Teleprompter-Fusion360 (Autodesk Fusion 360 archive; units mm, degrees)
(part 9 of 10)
sketch "Skizze105" plane through (0, 0, 0) normal (0, 0, -1) x axis (1, 0, 0)
  line L1 (47.0031, -126.3404) -> (155.5031, -126.3404)
  line L2 (35.0031, -31.3404) -> (35.0031, -114.3404)
  line L3 (155.5031, -19.3404) -> (47.0031, -19.3404)
  line L4 (167.5031, -114.3404) -> (167.5031, -31.3404)
  line L5 (191.5031, -31.3404) -> (191.5031, -114.3404)
  line L6 (312.0031, -19.3404) -> (203.5031, -19.3404)
  line L7 (324.0031, -114.3404) -> (324.0031, -31.3404)
  line L8 (203.5031, -126.3404) -> (312.0031, -126.3404)
  line L9 (137.0031, -323.7) -> (137.0031, -279.3404)
  line L10 (154.0031, -323.7) -> (137.0031, -323.7)
  line L11 (154.0031, -311.7) -> (154.0031, -323.7)
  line L12 (171.0031, -311.7) -> (154.0031, -311.7)
  line L13 (171.0031, -323.7) -> (171.0031, -311.7)
  line L14 (188.0031, -323.7) -> (171.0031, -323.7)
  line L15 (188.0031, -311.7) -> (188.0031, -323.7)
  line L16 (205.0031, -311.7) -> (188.0031, -311.7)
  line L17 (205.0031, -323.7) -> (205.0031, -311.7)
  line L18 (222.0031, -323.7) -> (205.0031, -323.7)
  line L19 (222.0031, -279.3404) -> (222.0031, -323.7)
  line L20 (374.0031, -255.3404) -> (246.0031, -255.3404)
  line L21 (374.0031, -240.1877) -> (374.0031, -255.3404)
  line L22 (366.2457, -240.1877) -> (374.0031, -240.1877)
  line L23 (362.0031, -220.3404) -> (362.0031, -235.9451)
  line L24 (361.0031, -220.3404) -> (362.0031, -220.3404)
  line L25 (358.0031, -167.3404) -> (358.0031, -217.3404)
  line L26 (362.0031, -164.3404) -> (361.0031, -164.3404)
  line L27 (362.0031, -134.383) -> (362.0031, -164.3404)
  line L28 (374.0031, -130.1404) -> (366.2457, -130.1404)
  line L29 (374.0031, -95.9404) -> (374.0031, -130.1404)
  line L30 (366.2457, -95.9404) -> (374.0031, -95.9404)
  line L31 (362.0031, -65.983) -> (362.0031, -91.6977)
  line L32 (374.0031, -61.7404) -> (366.2457, -61.7404)
  line L33 (374.0031, -27.5404) -> (374.0031, -61.7404)
  line L34 (366.2457, -27.5404) -> (374.0031, -27.5404)
  line L35 (362.0031, 2.417) -> (362.0031, -23.2977)
  line L36 (374.0031, 6.6596) -> (366.2457, 6.6596)
  line L37 (-2.9969, 18.6596) -> (362.0031, 18.6596)
  line L38 (-7.2396, 6.6596) -> (-14.9969, 6.6596)
  line L39 (-2.9969, -23.2977) -> (-2.9969, 2.417)
  line L40 (-14.9969, -27.5404) -> (-7.2396, -27.5404)
  line L41 (-14.9969, -61.7404) -> (-14.9969, -27.5404)
  line L42 (-7.2396, -61.7404) -> (-14.9969, -61.7404)
  line L43 (-2.9969, -91.6977) -> (-2.9969, -65.983)
  line L44 (-14.9969, -95.9404) -> (-7.2396, -95.9404)
  line L45 (-14.9969, -130.1404) -> (-14.9969, -95.9404)
  line L46 (-7.2396, -130.1404) -> (-14.9969, -130.1404)
  line L47 (-2.9969, -164.3404) -> (-2.9969, -134.383)
  line L48 (-2.9968, -164.3404) -> (-2.9969, -164.3404)
  line L49 (0.0031, -217.3404) -> (0.0031, -167.3404)
  line L50 (-2.9969, -220.3404) -> (-2.9968, -220.3404)
  line L51 (-2.9969, -235.9451) -> (-2.9969, -220.3404)
  line L52 (-14.9969, -240.1877) -> (-7.2396, -240.1877)
  line L53 (-14.9969, -255.3404) -> (-14.9969, -240.1877)
  line L54 (113.0031, -255.3404) -> (-14.9969, -255.3404)
  line L55 (159.8215, -317.5184) -> (154.0031, -311.7)
  line L56 (162.2315, -311.7) -> (154.0031, -311.7)
  line L57 (165.4986, -317.2045) -> (171.0031, -311.7)
  line L58 (178.7875, -311.7) -> (171.0031, -311.7)
  line L59 (193.6589, -317.3558) -> (188.0031, -311.7)
  line L60 (196.0016, -311.7) -> (188.0031, -311.7)
  line L61 (200.9258, -315.7773) -> (205.0031, -311.7)
  line L62 (210.7692, -311.7) -> (205.0031, -311.7)
  circle C1 centre (97.0031, -247.7641) radius 1.5
  circle C2 centre (179.5031, -138.3404) radius 1.5
  circle C3 centre (102.0031, -138.3404) radius 1.5
  circle C4 centre (262.0031, -247.7641) radius 1.5
  circle C5 centre (143.0031, -255.3404) radius 1.5
  circle C6 centre (257.0031, -138.3404) radius 1.5
  circle C7 centre (216.0031, -255.3404) radius 1.5
  circle C8 centre (179.4838, -56.3404) radius 1.5
  circle C9 centre (179.3775, -190) radius 20
  circle C10 centre (-8.9969, -113.0404) radius 4.5
  circle C11 centre (368.0031, -246.1877) radius 4.5
  circle C12 centre (368.0031, -44.6404) radius 4.5
  circle C13 centre (179.5031, -317.7) radius 4.5
  arc A1 centre (47.0031, -114.3404) radius 12 clockwise from (47.0031, -126.3404) to (35.0031, -114.3404)
  arc A2 centre (47.0031, -31.3404) radius 12 clockwise from (35.0031, -31.3404) to (47.0031, -19.3404)
  arc A3 centre (155.5031, -31.3404) radius 12 clockwise from (155.5031, -19.3404) to (167.5031, -31.3404)
  arc A4 centre (155.5031, -114.3404) radius 12 clockwise from (167.5031, -114.3404) to (155.5031, -126.3404)
  arc A5 centre (203.5031, -31.3404) radius 12 clockwise from (191.5031, -31.3404) to (203.5031, -19.3404)
  arc A6 centre (312.0031, -31.3404) radius 12 clockwise from (312.0031, -19.3404) to (324.0031, -31.3404)
  arc A7 centre (312.0031, -114.3404) radius 12 clockwise from (324.0031, -114.3404) to (312.0031, -126.3404)
  arc A8 centre (203.5031, -114.3404) radius 12 clockwise from (203.5031, -126.3404) to (191.5031, -114.3404)
  arc A9 centre (246.0031, -279.3404) radius 24 clockwise from (222.0031, -279.3404) to (246.0031, -255.3404)
  arc A10 centre (364.1244, -238.0664) radius 3 clockwise from (366.2457, -240.1877) to (362.0031, -235.9451)
  arc A11 centre (361.0031, -217.3404) radius 3 clockwise from (361.0031, -220.3404) to (358.0031, -217.3404)
  arc A12 centre (361.0031, -167.3404) radius 3 clockwise from (358.0031, -167.3404) to (361.0031, -164.3404)
  arc A13 centre (364.1244, -132.2617) radius 3 clockwise from (362.0031, -134.383) to (366.2457, -130.1404)
  arc A14 centre (364.1244, -93.8191) radius 3 clockwise from (366.2457, -95.9404) to (362.0031, -91.6977)
  arc A15 centre (364.1244, -63.8617) radius 3 clockwise from (362.0031, -65.983) to (366.2457, -61.7404)
  arc A16 centre (364.1244, -25.4191) radius 3 clockwise from (366.2457, -27.5404) to (362.0031, -23.2977)
  arc A17 centre (364.1244, 4.5383) radius 3 clockwise from (362.0031, 2.417) to (366.2457, 6.6596)
  arc A18 centre (362.0031, 6.6596) radius 12 clockwise from (362.0031, 18.6596) to (374.0031, 6.6596)
  arc A19 centre (-2.9969, 6.6596) radius 12 clockwise from (-14.9969, 6.6596) to (-2.9969, 18.6596)
  arc A20 centre (-5.1183, 4.5383) radius 3 clockwise from (-7.2396, 6.6596) to (-2.9969, 2.417)
  arc A21 centre (-5.1183, -25.4191) radius 3 clockwise from (-2.9969, -23.2977) to (-7.2396, -27.5404)
  arc A22 centre (-5.1183, -63.8617) radius 3 clockwise from (-7.2396, -61.7404) to (-2.9969, -65.983)
  arc A23 centre (-5.1183, -93.8191) radius 3 clockwise from (-2.9969, -91.6977) to (-7.2396, -95.9404)
  arc A24 centre (-5.1183, -132.2617) radius 3 clockwise from (-7.2396, -130.1404) to (-2.9969, -134.383)
  arc A25 centre (-2.9969, -167.3404) radius 3 clockwise from (-2.9968, -164.3404) to (0.0031, -167.3404)
  arc A26 centre (-2.9969, -217.3404) radius 3 clockwise from (0.0031, -217.3404) to (-2.9968, -220.3404)
  arc A27 centre (-5.1183, -238.0664) radius 3 clockwise from (-2.9969, -235.9451) to (-7.2396, -240.1877)
  arc A28 centre (113.0031, -279.3404) radius 24 clockwise from (113.0031, -255.3404) to (137.0031, -279.3404)
  circle C14 centre (213.5031, -317.7) radius 4.5
  circle C15 centre (145.5031, -317.7) radius 4.5
  circle C16 centre (368.0031, -113.0404) radius 4.5
  circle C17 centre (-8.9969, -44.6404) radius 4.5
  circle C18 centre (-8.9969, -246.1877) radius 4.5
  circle C19 centre (156.1597, -313.8567) radius 3.05
  circle C20 centre (168.8464, -313.8567) radius 3.05
  circle C21 centre (190.1597, -313.8567) radius 3.05
  circle C22 centre (202.8464, -313.8567) radius 3.05
  point P42 (154.0031, -311.7)
  point P130 (154.0031, -311.7)
  point P43 (171.0031, -311.7)
  point P133 (171.0031, -311.7)
  point P46 (188.0031, -311.7)
  point P136 (188.0031, -311.7)
  point P47 (205.0031, -311.7)
  point P139 (205.0031, -311.7)
  point P142 (156.1597, -313.8567)
  point P143 (168.8464, -313.8567)
  point P144 (190.1597, -313.8567)
  point P145 (202.8464, -313.8567)
  horizontal L56
  coincident P42 P130
  horizontal L58
  coincident P43 P133
  horizontal L60
  coincident P46 P136
  horizontal L62
  coincident P47 P139
  coincident L55 P142
  coincident L57 P143
  coincident L59 P144
  coincident L61 P145
  dimension "d621" angle L55 L56 = 45
  dimension "d622" angle L57 L58 = 135
  dimension "d623" angle L59 L60 = 45
  dimension "d624" angle L61 L62 = 135
  dimension "d625" diameter C19 = 6.1
  dimension "d626" diameter C20 = 6.1
  dimension "d627" diameter C21 = 6.1
  dimension "d628" diameter C22 = 6.1
  dimension "d629" distance P139 P145 = 3.05
  dimension "d630" distance P136 P144 = 3.05
  dimension "d631" distance P133 P143 = 3.05
  dimension "d632" distance P130 P142 = 3.05
extrude "Extrusion107" cut sketch "Skizze105" profile of L11 L12 L13 L15 L16 L17 C19 C20 C21 C22 against normal blind 17
sketch "Skizze106" plane through (0, 121.7, 0) normal (0, 1, 0) x axis (-1, 0, 0)
  line L1 (-137.0031, 150.455) -> (-137.0031, 163.3013)
  line L2 (14.9969, 150.455) -> (-137.0031, 150.455)
  line L3 (14.9969, 181.955) -> (14.9969, 150.455)
  line L4 (7.2396, 181.955) -> (14.9969, 181.955)
  line L5 (2.9969, 209.2124) -> (2.9969, 186.1976)
  line L6 (14.9969, 213.455) -> (7.2396, 213.455)
  line L7 (14.9969, 244.955) -> (14.9969, 213.455)
  line L8 (7.2396, 244.955) -> (14.9969, 244.955)
  line L9 (2.9969, 256.955) -> (2.9969, 249.1976)
  line L10 (-362.0031, 256.955) -> (2.9969, 256.955)
  line L11 (-362.0031, 249.1976) -> (-362.0031, 256.955)
  line L12 (-374.0031, 244.955) -> (-366.2457, 244.955)
  line L13 (-374.0031, 213.455) -> (-374.0031, 244.955)
  line L14 (-366.2457, 213.455) -> (-374.0031, 213.455)
  line L15 (-362.0031, 186.1976) -> (-362.0031, 209.2124)
  line L16 (-374.0031, 181.955) -> (-366.2457, 181.955)
  line L17 (-374.0031, 150.455) -> (-374.0031, 181.955)
  line L18 (-222.0031, 150.455) -> (-374.0031, 150.455)
  line L19 (-222.0031, 163.3017) -> (-222.0031, 150.455)
  line L20 (-222.0031, 202.455) -> (-222.0031, 189.1083)
  line L21 (-167.0031, 232.455) -> (-192.0031, 232.455)
  line L22 (-137.0031, 189.1087) -> (-137.0031, 202.455)
  line L23 (-247.0031, 138.455) -> (-247.0031, 146.1416)
  line L24 (-222.0031, 138.455) -> (-247.0031, 138.455)
  line L25 (-222.0031, 202.455) -> (-222.0031, 138.455)
  line L26 (-167.0031, 232.455) -> (-192.0031, 232.455)
  line L27 (-137.0031, 138.455) -> (-137.0031, 202.455)
  line L28 (-112.0031, 138.455) -> (-137.0031, 138.455)
  line L29 (-112.0031, 146.1416) -> (-112.0031, 138.455)
  line L30 (-87.0031, 150.455) -> (-107.6897, 150.455)
  line L31 (-87.0031, 232.955) -> (-87.0031, 150.455)
  line L32 (-248.0031, 256.955) -> (-111.0031, 256.955)
  line L33 (-272.0031, 150.455) -> (-272.0031, 232.955)
  line L34 (-251.3164, 150.455) -> (-272.0031, 150.455)
  line L35 (-338.0031, 220.955) -> (-338.0031, 186.455)
  line L36 (-362.0031, 29.6373) -> (-362.0031, 250.199)
  line L37 (-21.0031, 186.455) -> (-21.0031, 220.955)
  line L38 (2.9969, 250.199) -> (2.9969, 29.6373)
  line L39 (-284.0031, 186.455) -> (-284.0031, 220.955)
  line L40 (-75.0031, 186.455) -> (-75.0031, 220.955)
  line L41 (-296.0031, 232.955) -> (-326.0031, 232.955)
  line L42 (-296.0031, 174.455) -> (-326.0031, 174.455)
  line L43 (-242.1041, 232.955) -> (-272.0031, 232.955)
  line L44 (-87.0031, 232.955) -> (-110.271, 232.955)
  line L45 (-33.0031, 232.955) -> (-63.0031, 232.955)
  line L46 (-33.0031, 174.455) -> (-63.0031, 174.455)
  circle C1 centre (-247.0031, 191.955) radius 2
  circle C2 centre (-112.0031, 191.955) radius 2
  circle C3 centre (-247.0031, 231.955) radius 2
  circle C4 centre (-112.0031, 231.955) radius 2
  arc A1 centre (5.1183, 184.0763) radius 3 clockwise from (7.2396, 181.955) to (2.9969, 186.1976)
  arc A2 centre (5.1183, 211.3337) radius 3 clockwise from (2.9969, 209.2124) to (7.2396, 213.455)
  arc A3 centre (5.1183, 247.0763) radius 3 clockwise from (7.2396, 244.955) to (2.9969, 249.1976)
  arc A4 centre (-364.1244, 247.0763) radius 3 clockwise from (-362.0031, 249.1976) to (-366.2457, 244.955)
  arc A5 centre (-364.1244, 211.3337) radius 3 clockwise from (-366.2457, 213.455) to (-362.0031, 209.2124)
  arc A6 centre (-364.1244, 184.0763) radius 3 clockwise from (-362.0031, 186.1976) to (-366.2457, 181.955)
  arc A7 centre (-217.2525, 176.205) radius 13.75 clockwise from (-222.0031, 163.3017) to (-222.0031, 189.1083)
  arc A8 centre (-192.0031, 202.455) radius 30 clockwise from (-222.0031, 202.455) to (-192.0031, 232.455)
  arc A9 centre (-167.0031, 202.455) radius 30 clockwise from (-167.0031, 232.455) to (-137.0031, 202.455)
  arc A10 centre (-141.7525, 176.205) radius 13.75 clockwise from (-137.0031, 189.1087) to (-137.0031, 163.3013)
  arc A11 centre (-249.1597, 148.2983) radius 3.05 clockwise from (-251.3164, 150.455) to (-247.0031, 146.1416)
  arc A12 centre (-192.0031, 202.455) radius 30 clockwise from (-222.0031, 202.455) to (-192.0031, 232.455)
  arc A13 centre (-167.0031, 202.455) radius 30 clockwise from (-167.0031, 232.455) to (-137.0031, 202.455)
  arc A14 centre (-109.8464, 148.2983) radius 3.05 clockwise from (-112.0031, 146.1416) to (-107.6897, 150.455)
  arc A15 centre (-111.0031, 232.955) radius 24 clockwise from (-111.0031, 256.955) to (-87.0031, 232.955)
  arc A16 centre (-248.0031, 232.955) radius 24 clockwise from (-272.0031, 232.955) to (-248.0031, 256.955)
  circle C5 centre (-124.5031, 144.455) radius 1.5
  circle C6 centre (-234.5031, 144.455) radius 1.5
  circle C7 centre (-247.0031, 231.955) radius 5
  circle C8 centre (-112.0031, 231.955) radius 5
  circle C9 centre (-112.0031, 191.955) radius 5
  circle C10 centre (-247.0031, 191.955) radius 5
  arc A17 centre (-326.0031, 220.955) radius 12 clockwise from (-338.0031, 220.955) to (-326.0031, 232.955)
  arc A18 centre (-296.0031, 220.955) radius 12 clockwise from (-296.0031, 232.955) to (-284.0031, 220.955)
  arc A19 centre (-296.0031, 186.455) radius 12 clockwise from (-284.0031, 186.455) to (-296.0031, 174.455)
  arc A20 centre (-326.0031, 186.455) radius 12 clockwise from (-326.0031, 174.455) to (-338.0031, 186.455)
  arc A21 centre (-63.0031, 220.955) radius 12 clockwise from (-75.0031, 220.955) to (-63.0031, 232.955)
  arc A22 centre (-33.0031, 220.955) radius 12 clockwise from (-33.0031, 232.955) to (-21.0031, 220.955)
  arc A23 centre (-33.0031, 186.455) radius 12 clockwise from (-21.0031, 186.455) to (-33.0031, 174.455)
  arc A24 centre (-63.0031, 186.455) radius 12 clockwise from (-63.0031, 174.455) to (-75.0031, 186.455)
  point P82 (-242.1041, 232.955)
  point P83 (-110.271, 232.955)
  perpendicular L10 L35
  perpendicular L2 L37
  vertical L39
  parallel L31 L40
  perpendicular L37 L41
  perpendicular L37 L42
  collinear L41 L43
  coincident C7 P82
  collinear L43 L44
  collinear L44 L45
  coincident C4 P83
  tangent L35 A17
  tangent L41 A17
  tangent L41 A18
  tangent L39 A18
  equal A17 A18
  tangent L39 A19
  tangent L42 A19
  equal A17 A19
  tangent L42 A20
  tangent L35 A20
  equal A17 A20
  tangent L40 A21
  tangent L45 A21
  equal A17 A21
  tangent L45 A22
  tangent L37 A22
  equal A17 A22
  tangent L37 A23
  tangent L46 A23
  equal A17 A23
  tangent L46 A24
  tangent L40 A24
  equal A17 A24
  dimension "d635" distance L35 L36 = 24
  dimension "d636" distance L37 L38 = 24 (= "d635")
  dimension "d637" distance L31 L40 = 12
  dimension "d638" distance L33 L39 = 12
  dimension "d639" distance L10 L41 = 24
  dimension "d640" distance L2 L42 = 24
  dimension "d641" radius A17 = 12
extrude "Extrusion108" cut sketch "Skizze106" profile of L35 L37 L39 L40 L45 L46 A17 A18 A19 A20 A21 A22 A23 A24 against normal blind 20
sketch "Skizze107" plane through (0, 323.7, 0) normal (0, 1, 0) x axis (-1, 0, 0)
  line L1 (-205.0031, 0) -> (-205.0031, 7.6866)
  line L2 (-188.0031, 0) -> (-205.0031, 0)
  line L3 (-188.0031, 7.6866) -> (-188.0031, 0)
  line L4 (-175.3164, 12) -> (-183.6897, 12)
  line L5 (-171.0031, 0) -> (-171.0031, 7.6866)
  line L6 (-154.0031, 0) -> (-171.0031, 0)
  line L7 (-154.0031, 7.6866) -> (-154.0031, 0)
  line L8 (-137.0031, 12) -> (-149.6897, 12)
  line L9 (-137.0031, 138.455) -> (-137.0031, 12)
  line L10 (-149.6897, 138.455) -> (-137.0031, 138.455)
  line L11 (-154.0031, 150.455) -> (-154.0031, 142.7684)
  line L12 (-171.0031, 150.455) -> (-154.0031, 150.455)
  line L13 (-171.0031, 142.7684) -> (-171.0031, 150.455)
  line L14 (-183.6897, 138.455) -> (-175.3164, 138.455)
  line L15 (-188.0031, 150.455) -> (-188.0031, 142.7684)
  line L16 (-205.0031, 150.455) -> (-188.0031, 150.455)
  line L17 (-205.0031, 142.7684) -> (-205.0031, 150.455)
  line L18 (-222.0031, 138.455) -> (-209.3164, 138.455)
  line L19 (-222.0031, 12) -> (-222.0031, 138.455)
  line L20 (-209.3164, 12) -> (-222.0031, 12)
  line L21 (-171.0031, 114.455) -> (-188.0031, 114.455)
  line L22 (-161.0031, 46) -> (-161.0031, 104.455)
  line L23 (-188.0031, 36) -> (-171.0031, 36)
  line L24 (-198.0031, 104.455) -> (-198.0031, 46)
  circle C1 centre (-196.5031, 6) radius 4.5
  circle C2 centre (-162.5031, 144.455) radius 4.5
  circle C3 centre (-196.5031, 144.455) radius 4.5
  circle C4 centre (-162.5031, 6) radius 4.5
  arc A1 centre (-207.1597, 9.8433) radius 3.05 clockwise from (-209.3164, 12) to (-205.0031, 7.6866)
  arc A2 centre (-185.8464, 9.8433) radius 3.05 clockwise from (-188.0031, 7.6866) to (-183.6897, 12)
  arc A3 centre (-173.1597, 9.8433) radius 3.05 clockwise from (-175.3164, 12) to (-171.0031, 7.6866)
  arc A4 centre (-151.8464, 9.8433) radius 3.05 clockwise from (-154.0031, 7.6866) to (-149.6897, 12)
  arc A5 centre (-151.8464, 140.6117) radius 3.05 clockwise from (-149.6897, 138.455) to (-154.0031, 142.7684)
  arc A6 centre (-173.1597, 140.6117) radius 3.05 clockwise from (-171.0031, 142.7684) to (-175.3164, 138.455)
  arc A7 centre (-185.8464, 140.6117) radius 3.05 clockwise from (-183.6897, 138.455) to (-188.0031, 142.7684)
  arc A8 centre (-207.1597, 140.6117) radius 3.05 clockwise from (-205.0031, 142.7684) to (-209.3164, 138.455)
  arc A9 centre (-188.0031, 104.455) radius 10 clockwise from (-198.0031, 104.455) to (-188.0031, 114.455)
  arc A10 centre (-171.0031, 104.455) radius 10 clockwise from (-171.0031, 114.455) to (-161.0031, 104.455)
  arc A11 centre (-171.0031, 46) radius 10 clockwise from (-161.0031, 46) to (-171.0031, 36)
  arc A12 centre (-188.0031, 46) radius 10 clockwise from (-188.0031, 36) to (-198.0031, 46)
  horizontal L21
  vertical L22
  horizontal L23
  vertical L24
  tangent L24 A9
  tangent L21 A9
  tangent L21 A10
  tangent L22 A10
  equal A9 A10
  tangent L22 A11
  tangent L23 A11
  equal A9 A11
  tangent L23 A12
  tangent L24 A12
  equal A9 A12
  dimension "d644" distance L8 L23 = 24
  dimension "d645" distance L18 L21 = 24 (= "d644")
  dimension "d646" distance L19 L24 = 24
  dimension "d647" distance L9 L22 = 24 (= "d646")
  dimension "d648" radius A9 = 10
extrude "Extrusion109" cut sketch "Skizze107" profile of L21 L22 L23 L24 A9 A10 A11 A12 against normal blind 20
sketch "Skizze108" plane through (0, 133.7, 0) normal (0, 1, 0) x axis (-1, 0, 0)
  line L1 (-247.0031, 138.455) -> (-247.0031, 146.1416)
  line L2 (-222.0031, 138.455) -> (-247.0031, 138.455)
  line L3 (-222.0031, 202.455) -> (-222.0031, 138.455)
  line L4 (-167.0031, 232.455) -> (-192.0031, 232.455)
  line L5 (-137.0031, 138.455) -> (-137.0031, 202.455)
  line L6 (-112.0031, 138.455) -> (-137.0031, 138.455)
  line L7 (-112.0031, 146.1416) -> (-112.0031, 138.455)
  line L8 (-87.0031, 150.455) -> (-107.6897, 150.455)
  line L9 (-87.0031, 232.955) -> (-87.0031, 150.455)
  line L10 (-248.0031, 256.955) -> (-111.0031, 256.955)
  line L11 (-272.0031, 150.455) -> (-272.0031, 232.955)
  line L12 (-251.3164, 150.455) -> (-272.0031, 150.455)
  line L13 (-228.0031, 202.455) -> (-228.0031, 144.455)
  line L14 (-167.0031, 238.455) -> (-192.0031, 238.455)
  line L15 (-131.0031, 144.455) -> (-131.0031, 202.455)
  line L16 (-118.0398, 144.455) -> (-131.0031, 144.455)
  line L17 (-93.0031, 156.455) -> (-105.9258, 156.455)
  line L18 (-93.0031, 232.955) -> (-93.0031, 156.455)
  line L19 (-248.0031, 250.955) -> (-111.0031, 250.955)
  line L20 (-266.0031, 156.455) -> (-266.0031, 232.955)
  line L21 (-253.0803, 156.455) -> (-266.0031, 156.455)
  line L22 (-228.0031, 144.455) -> (-240.9664, 144.455)
  arc A1 centre (-249.1597, 148.2983) radius 3.05 clockwise from (-251.3164, 150.455) to (-247.0031, 146.1416)
  arc A2 centre (-192.0031, 202.455) radius 30 clockwise from (-222.0031, 202.455) to (-192.0031, 232.455)
  arc A3 centre (-167.0031, 202.455) radius 30 clockwise from (-167.0031, 232.455) to (-137.0031, 202.455)
  arc A4 centre (-109.8464, 148.2983) radius 3.05 clockwise from (-112.0031, 146.1416) to (-107.6897, 150.455)
  arc A5 centre (-111.0031, 232.955) radius 24 clockwise from (-111.0031, 256.955) to (-87.0031, 232.955)
  arc A6 centre (-248.0031, 232.955) radius 24 clockwise from (-272.0031, 232.955) to (-248.0031, 256.955)
  circle C1 centre (-124.5031, 144.455) radius 1.5
  circle C2 centre (-234.5031, 144.455) radius 1.5
  circle C3 centre (-247.0031, 231.955) radius 5
  circle C4 centre (-112.0031, 231.955) radius 5
  circle C5 centre (-112.0031, 191.955) radius 5
  circle C6 centre (-247.0031, 191.955) radius 5
  circle C7 centre (-179.5031, 189.955) radius 48.5
  arc A7 centre (-192.0031, 202.455) radius 36 clockwise from (-228.0031, 202.455) to (-192.0031, 238.455)
  arc A8 centre (-167.0031, 202.455) radius 36 clockwise from (-167.0031, 238.455) to (-131.0031, 202.455)
  arc A9 centre (-109.8464, 148.2983) radius 9.05 clockwise from (-118.0398, 144.455) to (-105.9258, 156.455)
  arc A10 centre (-111.0031, 232.955) radius 18 clockwise from (-111.0031, 250.955) to (-93.0031, 232.955)
  arc A11 centre (-248.0031, 232.955) radius 18 clockwise from (-266.0031, 232.955) to (-248.0031, 250.955)
  arc A12 centre (-249.1597, 148.2983) radius 9.05 clockwise from (-253.0803, 156.455) to (-240.9664, 144.455)
  tangent C7 L14
  tangent C7 L15
  tangent C7 L13
  dimension "d651" = 6
extrude "Extrusion110" cut sketch "Skizze108" profile of L3 A2 L4 A3 L5 C7 against normal blind 60
copy_paste_bodies "Körper kopieren/einfügen2"
move "Verschieben3"
move "Verschieben4"
sketch "Skizze109" plane through (0, 133.7, 0) normal (0, 1, 0) x axis (-1, 0, 0)
  line L1 (-137.0031, 138.455) -> (-137.0031, 166.5884)
  line L2 (-112.0031, 138.455) -> (-137.0031, 138.455)
  line L3 (-112.0031, 146.1416) -> (-112.0031, 138.455)
  line L4 (-87.0031, 150.455) -> (-107.6897, 150.455)
  line L5 (-87.0031, 232.955) -> (-87.0031, 150.455)
  line L6 (-248.0031, 256.955) -> (-111.0031, 256.955)
  line L7 (-272.0031, 150.455) -> (-272.0031, 232.955)
  line L8 (-251.3164, 150.455) -> (-272.0031, 150.455)
  line L9 (-247.0031, 138.455) -> (-247.0031, 146.1416)
  line L10 (-222.0031, 138.455) -> (-247.0031, 138.455)
  line L11 (-222.0031, 166.5884) -> (-222.0031, 138.455)
  line L12 (-87.0031, 150.455) -> (-272.0031, 150.455)
  arc A1 centre (-179.5031, 189.955) radius 48.5 clockwise from (-222.0031, 166.5884) to (-137.0031, 166.5884)
  arc A2 centre (-109.8464, 148.2983) radius 3.05 clockwise from (-112.0031, 146.1416) to (-107.6897, 150.455)
  arc A3 centre (-111.0031, 232.955) radius 24 clockwise from (-111.0031, 256.955) to (-87.0031, 232.955)
  arc A4 centre (-248.0031, 232.955) radius 24 clockwise from (-272.0031, 232.955) to (-248.0031, 256.955)
  arc A5 centre (-249.1597, 148.2983) radius 3.05 clockwise from (-251.3164, 150.455) to (-247.0031, 146.1416)
  circle C1 centre (-124.5031, 144.455) radius 1.5
  circle C2 centre (-234.5031, 144.455) radius 1.5
  circle C3 centre (-247.0031, 231.955) radius 5
  circle C4 centre (-112.0031, 231.955) radius 5
  circle C5 centre (-112.0031, 191.955) radius 5
  circle C6 centre (-247.0031, 191.955) radius 5
  point P17 (-272.0031, 150.455)
  point P29 (-272.0031, 150.455)
  point P10 (-87.0031, 150.455)
  point P30 (-87.0031, 150.455)
  coincident P17 P29
  coincident P10 P30
extrude "Extrusion111" cut sketch "Skizze109" profile of L1 L2 L3 A2 A5 L9 L10 L11 C1 C2 L12 against normal blind 30
sketch "Skizze110" plane through (0, 133.7, 0) normal (0, 1, 0) x axis (-1, 0, 0)
  line L1 (-222.0031, 150.455) -> (-247.0031, 150.455)
  line L2 (-222.0031, 166.5884) -> (-222.0031, 150.455)
  line L3 (-137.0031, 150.455) -> (-137.0031, 166.5884)
  line L4 (-112.0031, 150.455) -> (-137.0031, 150.455)
  line L5 (-87.0031, 150.455) -> (-107.6897, 150.455)
  line L6 (-87.0031, 232.955) -> (-87.0031, 150.455)
  line L7 (-248.0031, 256.955) -> (-111.0031, 256.955)
  line L8 (-272.0031, 150.455) -> (-272.0031, 232.955)
  line L9 (-251.3164, 150.455) -> (-272.0031, 150.455)
  line L10 (-141.7525, 162.455) -> (-217.2525, 162.455)
  line L11 (-217.2525, 189.955) -> (-141.7525, 189.955)
  line L12 (-217.2525, 190.155) -> (-141.7525, 190.155)
  line L13 (-141.7525, 162.255) -> (-217.2525, 162.255)
  line L14 (-235.5415, 189.955) -> (-217.2525, 189.955)
  line L15 (-122.7226, 190.155) -> (-235.5415, 189.955)
  line L16 (-137.0031, 150.455) -> (-222.0031, 150.455)
  line L17 (-87.0031, 150.455) -> (-272.0031, 150.455)
  circle C1 centre (-247.0031, 191.955) radius 5
  circle C2 centre (-112.0031, 191.955) radius 5
  circle C3 centre (-112.0031, 231.955) radius 5
  circle C4 centre (-247.0031, 231.955) radius 5
  arc A1 centre (-179.5031, 189.955) radius 48.5 clockwise from (-222.0031, 166.5884) to (-137.0031, 166.5884)
  arc A2 centre (-109.8464, 148.2983) radius 3.05 clockwise from (-112.0031, 150.455) to (-107.6897, 150.455)
  arc A3 centre (-111.0031, 232.955) radius 24 clockwise from (-111.0031, 256.955) to (-87.0031, 232.955)
  arc A4 centre (-248.0031, 232.955) radius 24 clockwise from (-272.0031, 232.955) to (-248.0031, 256.955)
  arc A5 centre (-249.1597, 148.2983) radius 3.05 clockwise from (-251.3164, 150.455) to (-247.0031, 150.455)
  arc A6 centre (-217.2525, 176.205) radius 13.75 clockwise from (-217.2525, 162.455) to (-217.2525, 189.955)
  arc A7 centre (-141.7525, 176.205) radius 13.75 clockwise from (-141.7525, 189.955) to (-141.7525, 162.455)
  arc A8 centre (-141.7525, 176.205) radius 13.95 clockwise from (-141.7525, 190.155) to (-141.7525, 162.255)
  arc A9 centre (-217.2525, 176.205) radius 13.95 clockwise from (-217.2525, 162.255) to (-217.2525, 190.155)
  point P25 (-217.2525, 189.955)
  point P37 (-217.2525, 189.955)
  point P7 (-222.0031, 150.455)
  point P40 (-222.0031, 150.455)
  point P11 (-137.0031, 150.455)
  point P41 (-137.0031, 150.455)
  point P22 (-272.0031, 150.455)
  point P42 (-272.0031, 150.455)
  point P15 (-87.0031, 150.455)
  point P43 (-87.0031, 150.455)
  coincident P25 P37
  tangent A6 L14
  coincident P7 P40
  coincident P11 P41
  coincident P22 P42
  coincident P15 P43
  dimension "d656" = 0.2
chamfer "Fase16" distance 1.5
chamfer "Fase17" distance 1.5
extrude "Extrusion113" add of existing geometry blind 12
sketch "Skizze111" plane through (0, 121.7, 0) normal (0, -1, 0) x axis (1, 0, 0)
  line L1 (272.0031, 150.455) -> (251.3164, 150.455)
  line L2 (272.0031, 232.955) -> (272.0031, 150.455)
  line L3 (111.0031, 256.955) -> (248.0031, 256.955)
  line L4 (87.0031, 150.455) -> (87.0031, 232.955)
  line L5 (107.6897, 150.455) -> (87.0031, 150.455)
  line L6 (112.0031, 138.455) -> (112.0031, 150.455)
  line L7 (137.0031, 138.455) -> (112.0031, 138.455)
  line L8 (137.0031, 166.5884) -> (137.0031, 138.455)
  line L9 (222.0031, 138.455) -> (222.0031, 166.5884)
  line L10 (247.0031, 138.455) -> (222.0031, 138.455)
  line L11 (247.0031, 150.455) -> (247.0031, 138.455)
  arc A1 centre (249.1597, 148.2983) radius 3.05 clockwise from (247.0031, 150.455) to (251.3164, 150.455)
  arc A2 centre (248.0031, 232.955) radius 24 clockwise from (248.0031, 256.955) to (272.0031, 232.955)
  arc A3 centre (111.0031, 232.955) radius 24 clockwise from (87.0031, 232.955) to (111.0031, 256.955)
  arc A4 centre (109.8464, 148.2983) radius 3.05 clockwise from (107.6897, 150.455) to (112.0031, 150.455)
  arc A5 centre (179.5031, 189.955) radius 48.5 clockwise from (137.0031, 166.5884) to (222.0031, 166.5884)
  circle C1 centre (112.0031, 191.955) radius 2
  circle C2 centre (112.0031, 231.955) radius 2
  circle C3 centre (247.0031, 191.955) radius 2
  circle C4 centre (247.0031, 231.955) radius 2
  circle C5 centre (249.1597, 148.2983) radius 3.05
  circle C6 centre (109.8464, 148.2983) radius 3.05
  point P2 (251.3164, 150.455)
  point P14 (112.0031, 150.455)
  concentric A1 C5
  coincident P2 C5
  concentric A4 C6
  coincident P14 C6
extrude "Extrusion114" cut sketch "Skizze111" profile of L6 L11 C5 C6 against normal blind 20
sketch "Skizze112" plane through (0, 121.7, 0) normal (0, -1, 0) x axis (1, 0, 0)
  line L1 (112.0031, 138.455) -> (112.0031, 146.1416)
  line L2 (137.0031, 138.455) -> (112.0031, 138.455)
  line L3 (137.0031, 166.5884) -> (137.0031, 138.455)
  line L4 (222.0031, 138.455) -> (222.0031, 166.5884)
  line L5 (247.0031, 138.455) -> (222.0031, 138.455)
  line L6 (247.0031, 146.1416) -> (247.0031, 138.455)
  line L7 (272.0031, 150.455) -> (251.3164, 150.455)
  line L8 (272.0031, 232.955) -> (272.0031, 150.455)
  line L9 (111.0031, 256.955) -> (248.0031, 256.955)
  line L10 (87.0031, 150.455) -> (87.0031, 232.955)
  line L11 (107.6897, 150.455) -> (87.0031, 150.455)
  line L12 (87.0031, 150.455) -> (272.0031, 150.455)
  line L13 (112.0031, 150.455) -> (112.0031, 138.455)
  line L14 (247.0031, 150.455) -> (247.0031, 138.455)
  line L15 (137.0031, 150.455) -> (112.0031, 138.455)
  line L16 (112.0031, 150.455) -> (137.0031, 138.455)
  line L17 (247.0031, 150.455) -> (222.0031, 138.455)
  line L18 (222.0031, 150.455) -> (247.0031, 138.455)
  circle C1 centre (247.0031, 231.955) radius 2
  circle C2 centre (247.0031, 191.955) radius 2
  circle C3 centre (112.0031, 231.955) radius 2
  circle C4 centre (112.0031, 191.955) radius 2
  arc A1 centre (109.8464, 148.2983) radius 3.05 clockwise from (107.6897, 150.455) to (112.0031, 146.1416)
  arc A2 centre (179.5031, 189.955) radius 48.5 clockwise from (137.0031, 166.5884) to (222.0031, 166.5884)
  arc A3 centre (249.1597, 148.2983) radius 3.05 clockwise from (247.0031, 146.1416) to (251.3164, 150.455)
  arc A4 centre (248.0031, 232.955) radius 24 clockwise from (248.0031, 256.955) to (272.0031, 232.955)
  arc A5 centre (111.0031, 232.955) radius 24 clockwise from (87.0031, 232.955) to (111.0031, 256.955)
  circle C5 centre (234.5031, 144.455) radius 1.5
  circle C6 centre (124.5031, 144.455) radius 1.5
  point P19 (272.0031, 150.455)
  point P27 (272.0031, 150.455)
  point P26 (87.0031, 150.455)
  point P28 (87.0031, 150.455)
  point P9 (112.0031, 138.455)
  point P29 (112.0031, 138.455)
  point P30 (112.0031, 150.455)
  point P15 (247.0031, 138.455)
  point P31 (247.0031, 138.455)
  point P32 (247.0031, 150.455)
  point P33 (137.0031, 150.455)
  point P10 (137.0031, 138.455)
  point P34 (137.0031, 138.455)
  point P14 (222.0031, 138.455)
  point P35 (222.0031, 138.455)
  point P36 (247.0031, 138.455)
  point P38 (234.5031, 144.455)
  point P39 (124.5031, 144.455)
  coincident P19 P27
  coincident P26 P28
  coincident P9 P29
  midpoint A1 P30
  coincident P15 P31
  midpoint A3 P32
  coincident L12 P33
  coincident L3 P33
  coincident P10 P34
  coincident P14 P35
  coincident P15 P36
  midpoint L18 P38
  midpoint L16 P39
  dimension "d665" diameter C5 = 3
  dimension "d666" diameter C6 = 3
extrude "Extrusion115" cut sketch "Skizze112" profile of C5 C6 against normal blind 15
chamfer "Fase18" distance 3
chamfer "Fase19" distance 2
chamfer "Fase20" distance 1
offset_faces "Flächen versetzen5" distance -0.1
sketch "Skizze113" plane through (0, 225.3404, 0) normal (0, 1, 0) x axis (-1, 0, 0)
  line L1 (-355.5031, 14.2) -> (-3.5031, 14.2)
  line L2 (-355.5031, 4.8) -> (-355.5031, 14.2)
  line L3 (-3.5031, 4.8) -> (-355.5031, 4.8)
  line L4 (-3.5031, 14.2) -> (-3.5031, 4.8)
  line L5 (-359.0031, 4.8) -> (-359.0031, 14.2)
  line L6 (-0.0031, 14.2) -> (-0.0031, 4.8)
  line L7 (-325.0031, 4) -> (-325.0031, 14.2)
  line L8 (-301.0031, 4) -> (-301.0031, 14.2)
  line L9 (-3.5031, 4) -> (-355.5031, 4)
  line L10 (-301.0031, 4) -> (-325.0031, 4)
  line L11 (-301.0031, 8) -> (-301.0031, 4)
  line L12 (-325.0031, 8) -> (-301.0031, 8)
  line L13 (-325.0031, 4) -> (-325.0031, 8)
  line L14 (-179.5031, 22.1076) -> (-179.5031, 4)
  line L15 (-34.0031, 4) -> (-34.0031, 8)
  line L16 (-34.0031, 8) -> (-58.0031, 8)
  line L17 (-58.0031, 4) -> (-58.0031, 14.2)
  line L18 (-34.0031, 4) -> (-34.0031, 14.2)
  line L19 (-58.0031, 4) -> (-34.0031, 4)
  point P10 (-325.0031, 14.2)
  point P11 (-301.0031, 14.2)
  point P14 (-325.0031, 4)
  point P15 (-301.0031, 4)
  point P19 (-179.5031, 4)
  point P26 (-34.0031, 14.2)
  point P24 (-58.0031, 14.2)
  point P22 (-34.0031, 4)
  point P25 (-58.0031, 4)
  point P16 (-301.0031, 4)
  point P27 (-58.0031, 4)
  point P17 (-301.0031, 8)
  point P23 (-58.0031, 8)
  point P18 (-325.0031, 8)
  point P21 (-34.0031, 8)
  coincident L1 P10
  perpendicular L3 L7
  coincident L1 P11
  perpendicular L3 L8
  coincident L9 P14
  coincident L9 P15
  horizontal L10
  vertical L11
  horizontal L12
  vertical L13
  midpoint L9 P19
  perpendicular L1 L14
  symmetric P10 L14 P26
  symmetric P11 L14 P24
  symmetric P14 L14 P22
  symmetric P15 L14 P25
  symmetric P16 L14 P27
  symmetric P17 L14 P23
  symmetric P18 L14 P21
  dimension "d673" distance L5 L7 = 34
  dimension "d674" distance L5 L8 = 58
  dimension "d675" distance P14 P18 = 4
extrude "Extrusion117" new body sketch "Skizze113" profile of L3 L7 L8 L9 L10 L11 L12 L13 L15 L16 L17 L18 L19 along normal blind 2 bodies "gummi-nupsi1", "gummi-nupsi2"
sketch "Skizze114" plane through (0, 0, 4) normal (0, 0, 1) x axis (-1, 0, 0)
  line L1 (2.9968, -220.3404) -> (2.9969, -220.3404)
  line L2 (-0.0031, -167.3404) -> (-0.0031, -217.3404)
  line L3 (2.9969, -164.3404) -> (2.9968, -164.3404)
  line L4 (2.9969, -150.3404) -> (2.9969, -164.3404)
  line L5 (-362.0031, -150.3404) -> (2.9969, -150.3404)
  line L6 (-362.0031, -164.3404) -> (-362.0031, -150.3404)
  line L7 (-361.0031, -164.3404) -> (-362.0031, -164.3404)
  line L8 (-358.0031, -217.3404) -> (-358.0031, -167.3404)
  line L9 (-362.0031, -220.3404) -> (-361.0031, -220.3404)
  line L10 (-362.0031, -226.3404) -> (-362.0031, -220.3404)
  line L11 (2.9969, -226.3404) -> (-362.0031, -226.3404)
  line L12 (2.9969, -220.3404) -> (2.9969, -226.3404)
  line L13 (-34.0031, -225.3404) -> (-58.0031, -225.3404)
  line L14 (-325.0031, -225.3404) -> (-301.0031, -225.3404)
  line L15 (-325.0031, -227.3404) -> (-301.0031, -227.3404)
  line L16 (-58.0031, -227.3404) -> (-34.0031, -227.3404)
  line L17 (-179.5031, -180.5742) -> (-179.5031, -226.3404)
  line L18 (-58.0031, -227.3404) -> (-34.0031, -227.3404)
  line L19 (-58.0031, -227.3404) -> (-34.0031, -227.3404)
  line L20 (-58.0031, -225.3404) -> (-58.0031, -227.3404)
  line L21 (-34.0031, -225.3404) -> (-58.0031, -225.3404)
  line L22 (-34.0031, -227.3404) -> (-34.0031, -225.3404)
  line L23 (-46.0031, -224.9775) -> (-46.0031, -227.3404)
  line L24 (-60.2391, -226.3404) -> (-31.767, -226.3404)
  line L25 (-298.767, -226.3404) -> (-327.2391, -226.3404)
  line L26 (-301.0031, -227.3404) -> (-325.0031, -227.3404)
  circle C1 centre (-179.3775, -190) radius 20
  arc A1 centre (2.9969, -217.3404) radius 3 clockwise from (2.9968, -220.3404) to (-0.0031, -217.3404)
  arc A2 centre (2.9969, -167.3404) radius 3 clockwise from (-0.0031, -167.3404) to (2.9968, -164.3404)
  arc A3 centre (-361.0031, -167.3404) radius 3 clockwise from (-361.0031, -164.3404) to (-358.0031, -167.3404)
  arc A4 centre (-361.0031, -217.3404) radius 3 clockwise from (-358.0031, -217.3404) to (-361.0031, -220.3404)
  arc A5 centre (-58.0031, -224.3404) radius 3 clockwise from (-58.0031, -227.3404) to (-60.2391, -226.3404)
  arc A6 centre (-34.0031, -224.3404) radius 3 clockwise from (-31.767, -226.3404) to (-34.0031, -227.3404)
  arc A7 centre (-325.0031, -224.3404) radius 3 clockwise from (-325.0031, -227.3404) to (-327.2391, -226.3404)
  arc A8 centre (-301.0031, -224.3404) radius 3 clockwise from (-298.767, -226.3404) to (-301.0031, -227.3404)
  point P31 (-179.5031, -226.3404)
  point P29 (-34.0031, -227.3404)
  point P33 (-34.0031, -227.3404)
  point P30 (-58.0031, -227.3404)
  point P34 (-58.0031, -227.3404)
  point P23 (-58.0031, -225.3404)
  point P36 (-58.0031, -225.3404)
  point P38 (-34.0031, -224.3404)
  point P39 (-46.0031, -227.3404)
  point P42 (-60.2391, -226.3404)
  point P43 (-31.767, -226.3404)
  point P47 (-325.0031, -227.3404)
  point P51 (-301.0031, -227.3404)
  point P48 (-325.0031, -227.3404)
  point P49 (-301.0031, -227.3404)
  point P45 (-298.767, -226.3404)
  point P44 (-327.2391, -226.3404)
  midpoint L11 P31
  perpendicular L11 L17
  coincident P29 P33
  coincident P30 P34
  horizontal L19
  vertical L20
  horizontal L21
  vertical L22
  coincident P23 P36
  tangent L19 A6
  coincident L22 P38
  midpoint L16 P39
  perpendicular L19 L23
  symmetric L23 A5 A6
  coincident L11 P42
  coincident L11 P43
  symmetric P29 L17 P47
  symmetric P30 L17 P51
  symmetric L17 P33 P48
  symmetric L17 P34 P49
  symmetric L17 P42 P45
  symmetric L17 A5 A8
  symmetric L17 A6 A7
  symmetric L17 P43 P44
  dimension "d680" diameter A6 = 6
extrude "Extrusion118" cut sketch "Skizze114" profile of L11 L15 L16 L18 L19 L20 L22 A6 A5 L24 L25 A7 L26 A8 along normal blind 9
sketch "Skizze115" plane through (-2.9969, 0, 0) normal (1, 0, 0) x axis (0, 1, 0)
  line L1 (-14.1296, 239.4473) -> (-16.2056, 241.5232)
  line L2 (-13.069, 240.508) -> (-14.1296, 239.4473)
  line L3 (-18.6596, 263) -> (-18.6596, 251.0692)
  line L4 (-18.6596, 263.0692) -> (-18.659, 263.0686)
  line L5 (-18.659, 263.0698) -> (-18.6596, 263.0692)
  line L6 (-10.2487, 267) -> (-14.6596, 267)
  line L7 (-3.2487, 268) -> (-3.2487, 267)
  line L8 (-4.7487, 268.5) -> (-3.2487, 268)
  line L9 (-14.6596, 268.5) -> (-4.7487, 268.5)
  line L10 (-20.1596, 251.0692) -> (-20.1596, 263)
  line L11 (-4.7893, 268.25) -> (-3.4987, 267.8198)
  line L12 (-14.6596, 268.25) -> (-4.7893, 268.25)
  line L13 (-19.9096, 251.0692) -> (-19.9096, 263)
  line L14 (-14.1296, 239.8008) -> (-16.0288, 241.7)
  line L15 (-13.2457, 240.6847) -> (-14.3064, 239.6241)
  line L16 (-18.9096, 262.9656) -> (-18.9096, 251.0692)
  line L17 (-19.0132, 263.0692) -> (-18.9096, 262.9656)
  line L18 (-18.9059, 263.1764) -> (-19.0132, 263.0692)
  line L19 (-9.9891, 267.25) -> (-14.6596, 267.25)
  line L20 (-3.4987, 268.0833) -> (-3.4987, 267)
  arc A1 centre (-15.5438, 242.9828) radius 3.5 clockwise from (-17.4864, 245.8942) to (-13.069, 240.508)
  arc A2 centre (-6.6596, 251.0692) radius 12 clockwise from (-17.4864, 245.8942) to (-18.6596, 251.0692)
  arc A3 centre (-14.6596, 263) radius 4 clockwise from (-18.6596, 263) to (-18.659, 263.0686)
  arc A4 centre (-14.6596, 263) radius 4 clockwise from (-18.659, 263.0698) to (-14.6596, 267)
  arc A5 centre (-6.7487, 267) radius 3.5 clockwise from (-3.2487, 267) to (-10.2487, 267)
  arc A6 centre (-14.6596, 263) radius 5.5 clockwise from (-20.1596, 263) to (-14.6596, 268.5)
  arc A7 centre (-6.6596, 251.0692) radius 13.5 clockwise from (-16.2056, 241.5232) to (-20.1596, 251.0692)
  arc A8 centre (-14.6596, 263) radius 5.25 clockwise from (-19.9096, 263) to (-14.6596, 268.25)
  arc A9 centre (-6.6596, 251.0692) radius 13.25 clockwise from (-16.0288, 241.7) to (-19.9096, 251.0692)
  arc A10 centre (-15.5438, 242.9828) radius 3.25 clockwise from (-17.579, 245.5167) to (-13.2457, 240.6847)
  arc A11 centre (-6.6596, 251.0692) radius 12.25 clockwise from (-17.579, 245.5167) to (-18.9096, 251.0692)
  arc A12 centre (-14.6596, 263) radius 4.25 clockwise from (-18.9059, 263.1764) to (-14.6596, 267.25)
  arc A13 centre (-6.7487, 267) radius 3.25 clockwise from (-3.4987, 267) to (-9.9891, 267.25)
  point P45 (-14.3064, 239.6241)
  point P31 (-14.1296, 239.8008)
  point P46 (-3.4987, 268.0833)
  point P23 (-3.4987, 267.8198)
  parallel L8 L11
  parallel L9 L12
  concentric A6 A8
  parallel L10 L13
  concentric A7 A9
  parallel L1 L14
  parallel L2 L15
  concentric A1 A10
  concentric A2 A11
  parallel L3 L16
  parallel L4 L17
  parallel L5 L18
  concentric A4 A12
  parallel L6 L19
  concentric A5 A13
  parallel L7 L20
  tangent L13 A9
  tangent L12 A8
  tangent L15 A10
  tangent A8 L13
  tangent A9 L14
  tangent A11 L16
  tangent A12 L19
  tangent A13 L20
  coincident L1 P45
  coincident P31 L15
  coincident L8 P46
  coincident P23 L20
extrude "Extrusion119" cut sketch "Skizze115" profile of L1 L2 A1 A2 L3 A3 L4 L5 A4 L6 A5 L7 L8 L16 L15 L20 A10 A11 L17 L18 A12 L19 A13 against normal blind 12
sketch "Skizze116" plane through (362.0031, 0, 0) normal (-1, 0, 0) x axis (0, -1, 0)
  line L1 (3.2948, 266.4342) -> (9.4921, 268.5)
  line L2 (14.6596, 267) -> (10.2487, 267)
  line L3 (18.6596, 263.0692) -> (18.659, 263.0698)
  line L4 (18.659, 263.0686) -> (18.6596, 263.0692)
  line L5 (18.6596, 251.0692) -> (18.6596, 263)
  line L6 (14.1296, 239.4473) -> (13.069, 240.508)
  line L7 (16.2056, 241.5232) -> (14.1296, 239.4473)
  line L8 (20.1596, 263) -> (20.1596, 251.0692)
  line L9 (9.4921, 268.5) -> (14.6596, 268.5)
  line L10 (14.6596, 267.25) -> (9.9891, 267.25)
  line L11 (3.5826, 266.2666) -> (9.5327, 268.25)
  line L12 (9.5327, 268.25) -> (14.6596, 268.25)
  line L13 (19.9096, 263) -> (19.9096, 251.0692)
  line L14 (16.0288, 241.7) -> (14.1296, 239.8008)
  line L15 (14.3064, 239.6241) -> (13.2457, 240.6847)
  line L16 (18.9096, 251.0692) -> (18.9096, 262.9656)
  line L17 (18.9096, 262.9656) -> (19.0132, 263.0692)
  line L18 (19.0132, 263.0692) -> (18.9059, 263.1764)
  line L19 (18.9096, 262.9656) -> (18.9059, 263.1764)
  arc A1 centre (6.7487, 267) radius 3.5 clockwise from (10.2487, 267) to (3.2948, 266.4342)
  arc A2 centre (14.6596, 263) radius 4 clockwise from (14.6596, 267) to (18.659, 263.0698)
  arc A3 centre (14.6596, 263) radius 4 clockwise from (18.659, 263.0686) to (18.6596, 263)
  arc A4 centre (6.6596, 251.0692) radius 12 clockwise from (18.6596, 251.0692) to (17.4864, 245.8942)
  arc A5 centre (15.5438, 242.9828) radius 3.5 clockwise from (13.069, 240.508) to (17.4864, 245.8942)
  arc A6 centre (6.6596, 251.0692) radius 13.5 clockwise from (20.1596, 251.0692) to (16.2056, 241.5232)
  arc A7 centre (14.6596, 263) radius 5.5 clockwise from (14.6596, 268.5) to (20.1596, 263)
  arc A8 centre (14.6596, 263) radius 4.25 clockwise from (14.6596, 267.25) to (18.9059, 263.1764)
  arc A9 centre (6.7487, 267) radius 3.25 clockwise from (9.9891, 267.25) to (3.5352, 266.5144)
  arc A10 centre (14.6596, 263) radius 5.25 clockwise from (14.6596, 268.25) to (19.9096, 263)
  arc A11 centre (6.6596, 251.0692) radius 13.25 clockwise from (19.9096, 251.0692) to (16.0288, 241.7)
  arc A12 centre (15.5438, 242.9828) radius 3.25 clockwise from (13.2457, 240.6847) to (17.579, 245.5167)
  arc A13 centre (6.6596, 251.0692) radius 12.25 clockwise from (18.9096, 251.0692) to (17.579, 245.5167)
  point P43 (14.3064, 239.6241)
  point P35 (14.1296, 239.8008)
  point P44 (3.5352, 266.5144)
  point P27 (3.5826, 266.2666)
  concentric A2 A8
  parallel L2 L10
  concentric A1 A9
  parallel L1 L11
  parallel L9 L12
  concentric A7 A10
  parallel L8 L13
  concentric A6 A11
  parallel L7 L14
  parallel L6 L15
  concentric A5 A12
  concentric A4 A13
  parallel L5 L16
  parallel L4 L17
  parallel L3 L18
  tangent L13 A11
  tangent A8 L10
  tangent A10 L13
  tangent L12 A10
  tangent A11 L14
  tangent L15 A12
  tangent A13 L16
  coincident L7 P43
  coincident P35 L15
  coincident L1 P44
  coincident P27 A9
extrude "Extrusion120" cut sketch "Skizze116" profile of L1 A1 L2 A2 L3 L4 A3 L5 A4 A5 L6 L7 L10 A8 A9 L15 A12 A13 L16 L19 against normal blind 12
offset_faces "Flächen versetzen6" distance 5
offset_faces "Flächen versetzen7" distance 5
offset_faces "Flächen versetzen8" distance -0.1
offset_faces "Flächen versetzen9" distance -0.1
offset_faces "Flächen versetzen10" distance -0.1
offset_faces "Flächen versetzen11" distance -0.1
offset_faces "Flächen versetzen12" distance -0.1
offset_faces "Flächen versetzen13" distance -0.1
offset_faces "Flächen versetzen14" distance -0.1
offset_faces "Flächen versetzen15" distance -0.1
offset_faces "Flächen versetzen16" distance -0.1
offset_faces "Flächen versetzen17" distance -0.1
offset_faces "Flächen versetzen18" distance -0.1
offset_faces "Flächen versetzen19" distance -0.1
offset_faces "Flächen versetzen20" distance -0.1
offset_faces "Flächen versetzen21" distance -0.1
offset_faces "Flächen versetzen22" distance -0.1
offset_faces "Flächen versetzen23" distance -0.1
offset_faces "Flächen versetzen24" distance -0.1
offset_faces "Flächen versetzen25" distance -0.1
offset_faces "Flächen versetzen26" distance -0.1
offset_faces "Flächen versetzen27" distance -0.1
offset_faces "Flächen versetzen28" distance -0.1
offset_faces "Flächen versetzen29" distance -0.1
offset_faces "Flächen versetzen30" distance -0.1
offset_faces "Flächen versetzen31" distance -0.1
sketch "Skizze118" plane through (0, 121.7, 0) normal (0, 1, 0) x axis (-1, 0, 0)
  line L1 (-137.0031, 150.455) -> (-137.0031, 163.3013)
  line L2 (14.9969, 150.455) -> (-137.0031, 150.455)
  line L3 (14.9969, 181.955) -> (14.9969, 150.455)
  line L4 (7.2396, 181.955) -> (14.9969, 181.955)
  line L5 (2.9969, 209.2124) -> (2.9969, 186.1976)
  line L6 (14.9969, 213.455) -> (7.2396, 213.455)
  line L7 (14.9969, 244.955) -> (14.9969, 213.455)
  line L8 (7.2396, 244.955) -> (14.9969, 244.955)
  line L9 (2.9969, 256.955) -> (2.9969, 249.1976)
  line L10 (-362.0031, 256.955) -> (2.9969, 256.955)
  line L11 (-362.0031, 249.1976) -> (-362.0031, 256.955)
  line L12 (-374.0031, 244.955) -> (-366.2457, 244.955)
  line L13 (-374.0031, 213.455) -> (-374.0031, 244.955)
  line L14 (-366.2457, 213.455) -> (-374.0031, 213.455)
  line L15 (-362.0031, 186.1976) -> (-362.0031, 209.2124)
  line L16 (-374.0031, 181.955) -> (-366.2457, 181.955)
  line L17 (-374.0031, 150.455) -> (-374.0031, 181.955)
  line L18 (-222.0031, 150.455) -> (-374.0031, 150.455)
  line L19 (-222.0031, 163.3017) -> (-222.0031, 150.455)
  line L20 (-338.0031, 220.955) -> (-338.0031, 186.455)
  line L21 (-296.0031, 232.955) -> (-326.0031, 232.955)
  line L22 (-284.0031, 186.455) -> (-284.0031, 220.955)
  line L23 (-326.0031, 174.455) -> (-296.0031, 174.455)
  line L24 (-75.0031, 220.955) -> (-75.0031, 186.455)
  line L25 (-33.0031, 232.955) -> (-63.0031, 232.955)
  line L26 (-21.0031, 186.455) -> (-21.0031, 220.955)
  line L27 (-63.0031, 174.455) -> (-33.0031, 174.455)
  arc A1 centre (-179.5031, 189.955) radius 48.5 clockwise from (-227.7571, 185.0772) to (-131.2489, 185.0783)
  arc A2 centre (-141.7525, 176.205) radius 13.75 clockwise from (-131.2489, 185.0783) to (-137.0031, 163.3013)
  arc A3 centre (5.1183, 184.0763) radius 3 clockwise from (7.2396, 181.955) to (2.9969, 186.1976)
  arc A4 centre (5.1183, 211.3337) radius 3 clockwise from (2.9969, 209.2124) to (7.2396, 213.455)
  arc A5 centre (5.1183, 247.0763) radius 3 clockwise from (7.2396, 244.955) to (2.9969, 249.1976)
  arc A6 centre (-364.1244, 247.0763) radius 3 clockwise from (-362.0031, 249.1976) to (-366.2457, 244.955)
  arc A7 centre (-364.1244, 211.3337) radius 3 clockwise from (-366.2457, 213.455) to (-362.0031, 209.2124)
  arc A8 centre (-364.1244, 184.0763) radius 3 clockwise from (-362.0031, 186.1976) to (-366.2457, 181.955)
  arc A9 centre (-217.2525, 176.205) radius 13.75 clockwise from (-222.0031, 163.3017) to (-227.7571, 185.0772)
  arc A10 centre (-326.0031, 220.955) radius 12 clockwise from (-338.0031, 220.955) to (-326.0031, 232.955)
  arc A11 centre (-296.0031, 220.955) radius 12 clockwise from (-296.0031, 232.955) to (-284.0031, 220.955)
  arc A12 centre (-296.0031, 186.455) radius 12 clockwise from (-284.0031, 186.455) to (-296.0031, 174.455)
  arc A13 centre (-326.0031, 186.455) radius 12 clockwise from (-326.0031, 174.455) to (-338.0031, 186.455)
  arc A14 centre (-63.0031, 220.955) radius 12 clockwise from (-75.0031, 220.955) to (-63.0031, 232.955)
  arc A15 centre (-33.0031, 220.955) radius 12 clockwise from (-33.0031, 232.955) to (-21.0031, 220.955)
  arc A16 centre (-33.0031, 186.455) radius 12 clockwise from (-21.0031, 186.455) to (-33.0031, 174.455)
  arc A17 centre (-63.0031, 186.455) radius 12 clockwise from (-63.0031, 174.455) to (-75.0031, 186.455)
  circle C1 centre (-247.0031, 191.955) radius 2
  circle C2 centre (-112.0031, 191.955) radius 2
  circle C3 centre (-247.0031, 231.955) radius 2
  circle C4 centre (-112.0031, 231.955) radius 2
extrude "Extrusion121" add sketch "Skizze118" profile of C1 C2 C3 C4 to an object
